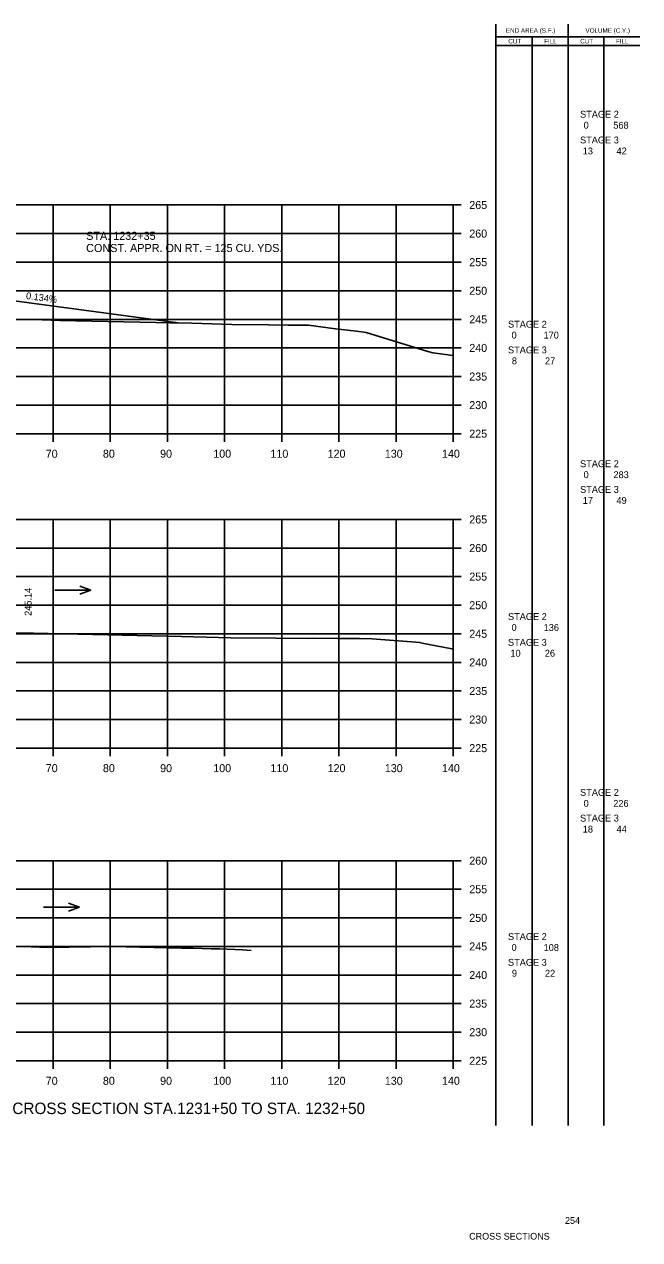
# Model space of a CAD drawing. Extents: x 1342547 to 1344156, y -1532351 to -1517216.
# Drawn here: x 1342767.9 to 1342875.5, y -1530020.4 to -1529807.8 of the extents above; entities that cross this region are included whole.
import ezdxf

# ---------------------------------------------------------------- set-up
doc = ezdxf.new("R2010")
doc.units = 0
for name, color, linetype in [('Level 2', 7, 'Continuous'), ('R_Axis', 7, 'Continuous'), ('R_Axis Annot', 7, 'Continuous'), ('R_Border Notes', 7, 'Continuous'), ('R_Draft', 7, 'Continuous'), ('R_Drive', 7, 'Continuous'), ('R_Exist Surface', 7, 'Continuous'), ('R_Grid', 7, 'Continuous'), ('R_Water', 7, 'Continuous'), ('R_Xsect Elev', 7, 'Continuous')]:
    doc.layers.add(name, color=color, linetype=linetype)

msp = doc.modelspace()

# ---------------------------------------------------------------- linework, layer by layer
at = {"layer": 'Level 2'}
for p, q in [((1342850.33, -1530000.43), (1342850.32, -1529807.83)), ((1342862.99, -1530000.43), (1342862.99, -1529807.83)), ((1342850.32, -1529809.99), (1342863.59, -1529809.99)), ((1342856.66, -1530000.43), (1342856.66, -1529809.99)), ((1342863.59, -1529809.99), (1342875.48, -1529809.99)), ((1342869.23, -1530000.43), (1342869.23, -1529809.99)), ((1342850.32, -1529811.55), (1342863.59, -1529811.55)), ((1342863.59, -1529811.55), (1342875.48, -1529811.55))]:
    msp.add_line(p, q, dxfattribs=at)
at = {"layer": 'R_Axis'}
for p, q in [((1342842.87, -1529879.43), (1342842.87, -1529839.43)), ((1342844.27, -1529839.43), (1342842.87, -1529839.43)), ((1342844.27, -1529844.43), (1342842.87, -1529844.43)), ((1342844.27, -1529849.43), (1342842.87, -1529849.43)), ((1342844.27, -1529854.43), (1342842.87, -1529854.43)), ((1342844.27, -1529859.43), (1342842.87, -1529859.43)), ((1342844.27, -1529864.43), (1342842.87, -1529864.43)), ((1342844.27, -1529869.43), (1342842.87, -1529869.43)), ((1342844.27, -1529874.43), (1342842.87, -1529874.43)), ((1342562.87, -1529879.43), (1342842.87, -1529879.43)), ((1342772.87, -1529880.83), (1342772.87, -1529879.43)), ((1342782.87, -1529880.83), (1342782.87, -1529879.43)), ((1342792.87, -1529880.83), (1342792.87, -1529879.43)), ((1342802.87, -1529880.83), (1342802.87, -1529879.43)), ((1342812.87, -1529880.83), (1342812.87, -1529879.43)), ((1342822.87, -1529880.83), (1342822.87, -1529879.43)), ((1342832.87, -1529880.83), (1342832.87, -1529879.43)), ((1342842.87, -1529880.83), (1342842.87, -1529879.43)), ((1342844.27, -1529879.43), (1342842.87, -1529879.43)), ((1342842.87, -1529934.43), (1342842.87, -1529894.43)), ((1342844.27, -1529894.43), (1342842.87, -1529894.43)), ((1342844.27, -1529899.43), (1342842.87, -1529899.43)), ((1342844.27, -1529904.43), (1342842.87, -1529904.43)), ((1342844.27, -1529909.43), (1342842.87, -1529909.43)), ((1342844.27, -1529914.43), (1342842.87, -1529914.43)), ((1342844.27, -1529919.43), (1342842.87, -1529919.43)), ((1342844.27, -1529924.43), (1342842.87, -1529924.43)), ((1342844.27, -1529929.43), (1342842.87, -1529929.43)), ((1342562.87, -1529934.43), (1342842.87, -1529934.43)), ((1342772.87, -1529935.83), (1342772.87, -1529934.43)), ((1342782.87, -1529935.83), (1342782.87, -1529934.43)), ((1342792.87, -1529935.83), (1342792.87, -1529934.43)), ((1342802.87, -1529935.83), (1342802.87, -1529934.43)), ((1342812.87, -1529935.83), (1342812.87, -1529934.43)), ((1342822.87, -1529935.83), (1342822.87, -1529934.43)), ((1342832.87, -1529935.83), (1342832.87, -1529934.43)), ((1342842.87, -1529935.83), (1342842.87, -1529934.43)), ((1342844.27, -1529934.43), (1342842.87, -1529934.43)), ((1342842.87, -1529989.11), (1342842.87, -1529954.11)), ((1342844.27, -1529954.11), (1342842.87, -1529954.11)), ((1342844.27, -1529959.11), (1342842.87, -1529959.11)), ((1342844.27, -1529964.11), (1342842.87, -1529964.11)), ((1342844.27, -1529969.11), (1342842.87, -1529969.11)), ((1342844.27, -1529974.11), (1342842.87, -1529974.11)), ((1342844.27, -1529979.11), (1342842.87, -1529979.11)), ((1342844.27, -1529984.11), (1342842.87, -1529984.11)), ((1342562.87, -1529989.11), (1342842.87, -1529989.11)), ((1342772.87, -1529990.51), (1342772.87, -1529989.11)), ((1342782.87, -1529990.51), (1342782.87, -1529989.11)), ((1342792.87, -1529990.51), (1342792.87, -1529989.11)), ((1342802.87, -1529990.51), (1342802.87, -1529989.11)), ((1342812.87, -1529990.51), (1342812.87, -1529989.11)), ((1342822.87, -1529990.51), (1342822.87, -1529989.11)), ((1342832.87, -1529990.51), (1342832.87, -1529989.11)), ((1342842.87, -1529990.51), (1342842.87, -1529989.11)), ((1342844.27, -1529989.11), (1342842.87, -1529989.11))]:
    msp.add_line(p, q, dxfattribs=at)
at = {"layer": 'R_Drive'}
msp.add_lwpolyline([(1342747.36, -1529853.68), (1342794.77, -1529860.05)], dxfattribs=at)
msp.add_lwpolyline([(1342747.36, -1529853.68), (1342794.77, -1529860.05)], dxfattribs=at)
at = {"layer": 'R_Exist Surface'}
for points in [[(1342756.97, -1529859.4), (1342769.43, -1529859.48), (1342774.09, -1529859.63), (1342790.85, -1529859.98), (1342793.24, -1529860.02), (1342797.14, -1529860.11), (1342804.15, -1529860.34), (1342810.56, -1529860.38), (1342814.01, -1529860.44), (1342817.53, -1529860.47), (1342822.27, -1529861.1), (1342825.94, -1529861.51), (1342827.61, -1529861.74), (1342838.4, -1529865.04), (1342839.27, -1529865.31), (1342842.87, -1529865.76)], [(1342760.06, -1529914.12), (1342769.45, -1529914.34), (1342795.35, -1529914.91), (1342797.47, -1529914.96), (1342803.96, -1529915.12), (1342811.85, -1529915.21), (1342817.58, -1529915.25), (1342818.42, -1529915.18), (1342822.68, -1529915.24), (1342825.19, -1529915.23), (1342826.45, -1529915.28), (1342828.66, -1529915.31), (1342836.32, -1529915.88), (1342836.98, -1529915.93), (1342837.42, -1529916.04), (1342842.61, -1529917.03), (1342842.87, -1529917.06)], [(1342761.88, -1529968.89), (1342771.92, -1529969.28), (1342783.23, -1529969.15), (1342788.06, -1529969.26), (1342795.32, -1529969.4), (1342797.36, -1529969.43), (1342800.51, -1529969.52), (1342802, -1529969.55), (1342806.03, -1529969.7), (1342807.54, -1529969.8)]]:
    msp.add_lwpolyline(points, dxfattribs=at)
at = {"layer": 'R_Grid'}
for p, q in [((1342562.87, -1529839.43), (1342842.87, -1529839.43)), ((1342772.87, -1529879.43), (1342772.87, -1529839.43)), ((1342782.87, -1529879.43), (1342782.87, -1529839.43)), ((1342792.87, -1529879.43), (1342792.87, -1529839.43)), ((1342802.87, -1529879.43), (1342802.87, -1529839.43)), ((1342812.87, -1529879.43), (1342812.87, -1529839.43)), ((1342822.87, -1529879.43), (1342822.87, -1529839.43)), ((1342832.87, -1529879.43), (1342832.87, -1529839.43)), ((1342842.87, -1529879.43), (1342842.87, -1529839.43)), ((1342562.87, -1529844.43), (1342842.87, -1529844.43)), ((1342562.87, -1529849.43), (1342842.87, -1529849.43)), ((1342562.87, -1529854.43), (1342842.87, -1529854.43)), ((1342562.87, -1529859.43), (1342842.87, -1529859.43)), ((1342562.87, -1529864.43), (1342842.87, -1529864.43)), ((1342562.87, -1529869.43), (1342842.87, -1529869.43)), ((1342562.87, -1529874.43), (1342842.87, -1529874.43)), ((1342562.87, -1529879.43), (1342842.87, -1529879.43)), ((1342562.87, -1529894.43), (1342842.87, -1529894.43)), ((1342772.87, -1529934.43), (1342772.87, -1529894.43)), ((1342782.87, -1529934.43), (1342782.87, -1529894.43)), ((1342792.87, -1529934.43), (1342792.87, -1529894.43)), ((1342802.87, -1529934.43), (1342802.87, -1529894.43)), ((1342812.87, -1529934.43), (1342812.87, -1529894.43)), ((1342822.87, -1529934.43), (1342822.87, -1529894.43)), ((1342832.87, -1529934.43), (1342832.87, -1529894.43)), ((1342842.87, -1529934.43), (1342842.87, -1529894.43)), ((1342562.87, -1529899.43), (1342842.87, -1529899.43)), ((1342562.87, -1529904.43), (1342842.87, -1529904.43)), ((1342562.87, -1529909.43), (1342842.87, -1529909.43)), ((1342562.87, -1529914.43), (1342842.87, -1529914.43)), ((1342562.87, -1529919.43), (1342842.87, -1529919.43)), ((1342562.87, -1529924.43), (1342842.87, -1529924.43)), ((1342562.87, -1529929.43), (1342842.87, -1529929.43)), ((1342562.87, -1529934.43), (1342842.87, -1529934.43)), ((1342562.87, -1529954.11), (1342842.87, -1529954.11)), ((1342772.87, -1529989.11), (1342772.87, -1529954.11)), ((1342782.87, -1529989.11), (1342782.87, -1529954.11)), ((1342792.87, -1529989.11), (1342792.87, -1529954.11)), ((1342802.87, -1529989.11), (1342802.87, -1529954.11)), ((1342812.87, -1529989.11), (1342812.87, -1529954.11)), ((1342822.87, -1529989.11), (1342822.87, -1529954.11)), ((1342832.87, -1529989.11), (1342832.87, -1529954.11)), ((1342842.87, -1529989.11), (1342842.87, -1529954.11)), ((1342562.87, -1529959.11), (1342842.87, -1529959.11)), ((1342562.87, -1529964.11), (1342842.87, -1529964.11)), ((1342562.87, -1529969.11), (1342842.87, -1529969.11)), ((1342562.87, -1529974.11), (1342842.87, -1529974.11)), ((1342562.87, -1529979.11), (1342842.87, -1529979.11)), ((1342562.87, -1529984.11), (1342842.87, -1529984.11)), ((1342562.87, -1529989.11), (1342842.87, -1529989.11))]:
    msp.add_line(p, q, dxfattribs=at)
at = {"layer": 'R_Water'}
for p, q in [((1342779.46, -1529906.77), (1342777.54, -1529906.07)), ((1342773.18, -1529906.77), (1342779.46, -1529906.77)), ((1342779.46, -1529906.77), (1342777.54, -1529907.47)), ((1342777.48, -1529962.24), (1342775.55, -1529961.54)), ((1342771.19, -1529962.24), (1342777.48, -1529962.24)), ((1342777.48, -1529962.24), (1342775.55, -1529962.94))]:
    msp.add_line(p, q, dxfattribs=at)

# ---------------------------------------------------------------- texts
at = {"layer": 'Level 2'}
for s, height, p in [('END AREA (S.F.)', 0.7937, (1342852.08, -1529809.31)), ('VOLUME (C.Y.)', 0.7937, (1342865.99, -1529809.31)), ('CUT', 0.794, (1342852.5, -1529811.17)), ('FILL', 0.794, (1342858.76, -1529811.17)), ('CUT', 0.794, (1342865.07, -1529811.17)), ('FILL', 0.794, (1342871.33, -1529811.17)), (' STAGE 2 ', 1.2, (1342864.6, -1529824.16)), ('0', 1.2, (1342865.67, -1529826.08)), ('568', 1.2, (1342870.86, -1529826.08)), (' STAGE 3 ', 1.2, (1342864.6, -1529828.66)), ('13', 1.2, (1342865.52, -1529830.58)), ('42', 1.2, (1342871.43, -1529830.58)), (' STAGE 2 ', 1.2, (1342852, -1529860.88)), ('0', 1.2, (1342853.07, -1529862.79)), ('170', 1.2, (1342858.66, -1529862.79)), (' STAGE 3 ', 1.2, (1342852, -1529865.38)), ('8', 1.2, (1342853.12, -1529867.29)), ('27', 1.2, (1342858.91, -1529867.29)), (' STAGE 2 ', 1.2, (1342864.6, -1529885.29)), ('0', 1.2, (1342865.67, -1529887.2)), ('283', 1.2, (1342870.89, -1529887.2)), (' STAGE 3 ', 1.2, (1342864.6, -1529889.79)), ('17', 1.2, (1342865.52, -1529891.7)), ('49', 1.2, (1342871.42, -1529891.7)), (' STAGE 2 ', 1.2, (1342852, -1529912.02)), ('0', 1.2, (1342853.07, -1529913.93)), ('136', 1.2, (1342858.68, -1529913.93)), (' STAGE 3 ', 1.2, (1342852, -1529916.52)), ('10', 1.2, (1342852.87, -1529918.43)), ('26', 1.2, (1342858.88, -1529918.43)), (' STAGE 2 ', 1.2, (1342864.6, -1529942.77)), ('0', 1.2, (1342865.67, -1529944.69)), ('226', 1.2, (1342870.85, -1529944.69)), (' STAGE 3 ', 1.2, (1342864.6, -1529947.27)), ('18', 1.2, (1342865.52, -1529949.19)), ('44', 1.2, (1342871.43, -1529949.19)), (' STAGE 2 ', 1.2, (1342852, -1529967.99)), ('0', 1.2, (1342853.07, -1529969.9)), ('108', 1.2, (1342858.67, -1529969.9)), (' STAGE 3 ', 1.2, (1342852, -1529972.49)), ('9', 1.2, (1342853.12, -1529974.4)), ('22', 1.2, (1342858.91, -1529974.4))]:
    msp.add_text(s, height=height, dxfattribs=at).set_placement(p)
at = {"layer": 'R_Axis Annot'}
for s, p in [('265', (1342845.67, -1529840.13)), ('260', (1342845.67, -1529845.13)), ('255', (1342845.67, -1529850.13)), ('250', (1342845.67, -1529855.13)), ('245', (1342845.67, -1529860.13)), ('240', (1342845.67, -1529865.13)), ('235', (1342845.67, -1529870.13)), ('230', (1342845.67, -1529875.13)), ('225', (1342845.67, -1529880.13)), ('70', (1342771.6, -1529883.63)), ('80', (1342781.6, -1529883.63)), ('90', (1342791.6, -1529883.63)), ('100', (1342800.9, -1529883.63)), ('110', (1342810.9, -1529883.63)), ('120', (1342820.9, -1529883.63)), ('130', (1342830.9, -1529883.63)), ('140', (1342840.9, -1529883.63)), ('265', (1342845.67, -1529895.13)), ('260', (1342845.67, -1529900.13)), ('255', (1342845.67, -1529905.13)), ('250', (1342845.67, -1529910.13)), ('245', (1342845.67, -1529915.13)), ('240', (1342845.67, -1529920.13)), ('235', (1342845.67, -1529925.13)), ('230', (1342845.67, -1529930.13)), ('225', (1342845.67, -1529935.13)), ('70', (1342771.6, -1529938.63)), ('80', (1342781.6, -1529938.63)), ('90', (1342791.6, -1529938.63)), ('100', (1342800.9, -1529938.63)), ('110', (1342810.9, -1529938.63)), ('120', (1342820.9, -1529938.63)), ('130', (1342830.9, -1529938.63)), ('140', (1342840.9, -1529938.63)), ('260', (1342845.67, -1529954.81)), ('255', (1342845.67, -1529959.81)), ('250', (1342845.67, -1529964.81)), ('245', (1342845.67, -1529969.81)), ('240', (1342845.67, -1529974.81)), ('235', (1342845.67, -1529979.81)), ('230', (1342845.67, -1529984.81)), ('225', (1342845.67, -1529989.81)), ('70', (1342771.6, -1529993.31)), ('80', (1342781.6, -1529993.31)), ('90', (1342791.6, -1529993.31)), ('100', (1342800.9, -1529993.31)), ('110', (1342810.9, -1529993.31)), ('120', (1342820.9, -1529993.31)), ('130', (1342830.9, -1529993.31)), ('140', (1342840.9, -1529993.31))]:
    msp.add_text(s, height=1.4, dxfattribs=at).set_placement(p)
at = {"layer": 'R_Border Notes'}
for s, height, p in [('STA. 1232+35 ', 1.4147, (1342778.67, -1529845.53)), ('STA. 1232+35 ', 1.4147, (1342778.67, -1529845.53)), ('CONST. APPR. ON RT. = 125 CU. YDS.', 1.4147, (1342778.67, -1529847.66)), ('CONST. APPR. ON RT. = 125 CU. YDS.', 1.4147, (1342778.67, -1529847.66)), ('254', 1.177, (1342862.41, -1530017.63)), ('CROSS SECTIONS', 1.1775, (1342845.65, -1530020.39))]:
    msp.add_text(s, height=height, dxfattribs=at).set_placement(p)
at = {"layer": 'R_Draft'}
msp.add_text('CROSS SECTION STA.1231+50 TO STA. 1232+50', height=2, dxfattribs=at).set_placement((1342765.76, -1529998.43))
at = {"layer": 'R_Xsect Elev'}
for s, rotation, p in [('0.134%', 352.344, (1342768.09, -1529855.86)), ('245.14', 90, (1342769.11, -1529911.29))]:
    msp.add_text(s, height=1.2, rotation=rotation, dxfattribs=at).set_placement(p)

doc.saveas('drawing.dxf')
